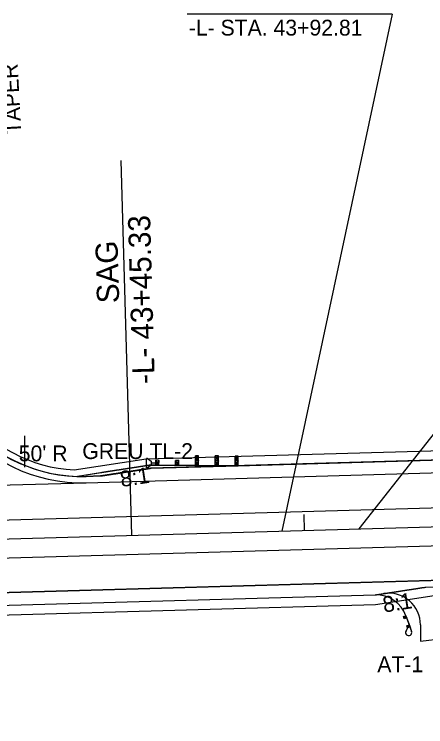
# Model space of a CAD drawing. Extents: x 1755545 to 1761252, y 736169 to 737766.
# Drawn here: x 1758991.6 to 1759121.4, y 736960.3 to 737185.3 of the extents above; entities that cross this region are included whole.
import ezdxf

# ---------------------------------------------------------------- set-up
doc = ezdxf.new("R2010")
doc.units = 0
for name, color, linetype in [('Exist Contamination Potential Cell', 7, 'Continuous'), ('Old_Level_1', 7, 'Continuous'), ('Old_Level_15', 7, 'Continuous'), ('Prop Dimension', 7, 'Continuous'), ('Prop Guardrail', 7, 'Continuous'), ('Prop Guardrail Anchor Unit CELL', 7, 'Continuous'), ('Prop Horizontal Alignment', 7, 'Continuous'), ('Prop Horizontal Alignment Tick Small', 7, 'Continuous'), ('Prop Lane Lines', 7, 'Continuous'), ('Prop Paved Shoulder', 7, 'Continuous'), ('Prop Shade Light', 7, 'Continuous'), ('Scratch_Level_5', 7, 'Continuous'), ('Scratch_Level_6', 7, 'Continuous')]:
    doc.layers.add(name, color=color, linetype=linetype)

msp = doc.modelspace()

# ---------------------------------------------------------------- linework, layer by layer
at = {"layer": 'Exist Contamination Potential Cell'}
for p, q in [((1759014.29, 737037.34), (1760207.22, 737071.22)), ((1757498.66, 736960.29), (1760222.11, 737037.63))]:
    msp.add_line(p, q, dxfattribs=at)
msp.add_arc((1759012.87, 737087.32), 50, 216.7448, 271.6265, dxfattribs=at)
at = {"layer": 'Old_Level_1'}
for p, q in [((1759119.74, 736992.48), (1759119.75, 736987.31)), ((1759119.75, 736987.31), (1759134.95, 736989.05))]:
    msp.add_line(p, q, dxfattribs=at)
msp.add_arc((1759109.74, 736992.46), 10, 0.1161, 98.7516, dxfattribs=at)
at = {"layer": 'Old_Level_15'}
msp.add_line((1759025.17, 737139.07), (1759028.53, 737020.74), dxfattribs=at)
at = {"layer": 'Prop Dimension'}
for p, q in [((1759110.79, 737185.26), (1759046.14, 737185.26)), ((1759110.79, 737185.26), (1759075.99, 737022.09)), ((1759169.57, 737111.19), (1759100.35, 737022.78))]:
    msp.add_line(p, q, dxfattribs=at)
at = {"layer": 'Prop Guardrail'}
for p, q in [((1759211.17, 737046.94), (1759062.23, 737042.71)), ((1758905.56, 736996.24), (1759105.48, 737001.92))]:
    msp.add_line(p, q, dxfattribs=at)
msp.add_arc((1759105.76, 736991.92), 10, 20.0067, 91.6265, dxfattribs=at)
at = {"layer": 'Prop Guardrail Anchor Unit CELL'}
for p, q in [((1759048.73, 737042.81), (1759048.76, 737045.84)), ((1759048.74, 737044.33), (1759049.76, 737045.84)), ((1759049.76, 737045.84), (1759048.76, 737045.84)), ((1759048.76, 737045.84), (1759049.74, 737044.32)), ((1759049.73, 737042.8), (1759049.76, 737045.84)), ((1759054.98, 737042.76), (1759055.01, 737045.8)), ((1759054.99, 737044.28), (1759056.01, 737045.79)), ((1759056.01, 737045.79), (1759055.01, 737045.8)), ((1759055.01, 737045.8), (1759055.99, 737044.27)), ((1759055.98, 737042.75), (1759056.01, 737045.79)), ((1759061.23, 737042.71), (1759061.26, 737045.75)), ((1759061.24, 737044.23), (1759062.26, 737045.74)), ((1759062.26, 737045.74), (1759061.26, 737045.75)), ((1759061.26, 737045.75), (1759062.24, 737044.22)), ((1759062.23, 737042.71), (1759062.26, 737045.74)), ((1759033.27, 737042.08), (1759033.3, 737045.02)), ((1759033.61, 737045.02), (1759033.3, 737045.02)), ((1759033.61, 737045.02), (1759034.77, 737044.15)), ((1759034.77, 737044.15), (1759034.76, 737042.93)), ((1759034.77, 737043.65), (1759036.24, 737043.63)), ((1759036.23, 737042.9), (1759036.25, 737044.42)), ((1759037.24, 737044.41), (1759036.23, 737042.9)), ((1759037.23, 737042.89), (1759036.24, 737044.42)), ((1759037.25, 737044.41), (1759036.25, 737044.42)), ((1759037.23, 737042.89), (1759037.25, 737044.41)), ((1759042.48, 737042.86), (1759042.49, 737044.37)), ((1759043.49, 737044.37), (1759042.48, 737042.86)), ((1759043.5, 737044.37), (1759042.49, 737044.37)), ((1759043.48, 737042.85), (1759042.49, 737044.37)), ((1759043.48, 737042.85), (1759043.5, 737044.37)), ((1759049.74, 737044.32), (1759048.73, 737042.81)), ((1759049.74, 737044.32), (1759048.74, 737044.33)), ((1759049.73, 737042.8), (1759048.74, 737044.33)), ((1759055.99, 737044.27), (1759054.98, 737042.76)), ((1759055.99, 737044.27), (1759054.99, 737044.28)), ((1759055.98, 737042.75), (1759054.99, 737044.28)), ((1759062.24, 737044.22), (1759061.23, 737042.71)), ((1759062.24, 737044.22), (1759061.24, 737044.23)), ((1759062.23, 737042.71), (1759061.24, 737044.23)), ((1759033.58, 737042.08), (1759033.27, 737042.08)), ((1759034.76, 737042.93), (1759033.58, 737042.08)), ((1759036.23, 737042.91), (1759034.76, 737042.93)), ((1759037.23, 737042.89), (1759036.23, 737042.9)), ((1759036.73, 737042.9), (1759061.73, 737042.71)), ((1759043.48, 737042.85), (1759042.48, 737042.86)), ((1759049.73, 737042.8), (1759048.73, 737042.81)), ((1759055.98, 737042.75), (1759054.98, 737042.76)), ((1759062.23, 737042.71), (1759061.23, 737042.71)), ((1759114.4, 736995.07), (1759115.16, 736995.34)), ((1759114.64, 736994.41), (1759114.4, 736995.07)), ((1759115.4, 736994.69), (1759114.4, 736995.07)), ((1759115.16, 736995.34), (1759114.64, 736994.41)), ((1759115.4, 736994.69), (1759114.64, 736994.41)), ((1759115.16, 736995.34), (1759116.37, 736992.01)), ((1759115.16, 736995.34), (1759115.4, 736994.69)), ((1759115.2, 736990.6), (1759115.8, 736991.52)), ((1759115.47, 736992.15), (1759116.22, 736992.42)), ((1759115.71, 736991.49), (1759115.47, 736992.15)), ((1759116.46, 736991.76), (1759115.47, 736992.15)), ((1759116.22, 736992.42), (1759115.71, 736991.49)), ((1759116.46, 736991.76), (1759115.71, 736991.49)), ((1759116.46, 736991.76), (1759116.13, 736991.64)), ((1759116.46, 736991.76), (1759116.13, 736991.64)), ((1759116.22, 736992.42), (1759116.46, 736991.76)), ((1759116.42, 736991.89), (1759116.37, 736992.01)), ((1759116.37, 736992.01), (1759116.96, 736990.4)), ((1759116.42, 736991.89), (1759116.37, 736992.01))]:
    msp.add_line(p, q, dxfattribs=at)
msp.add_ellipse((1759116.03, 736990.06), major_axis=(0.933, 0.34), ratio=0.995379, start_param=2.210226, end_param=6.283185, dxfattribs=at)
at = {"layer": 'Prop Horizontal Alignment'}
msp.add_line((1757285.64, 736971.25), (1760282.69, 737056.35), dxfattribs=at)
at = {"layer": 'Prop Horizontal Alignment Tick Small'}
msp.add_line((1759083.17, 737022.29), (1759083.03, 737027.29), dxfattribs=at)
at = {"layer": 'Prop Lane Lines'}
for p, q in [((1757285.47, 736977.25), (1760207.53, 737060.22)), ((1757285.81, 736965.25), (1760207.87, 737048.23)), ((1758821.01, 737031.85), (1759014.29, 737037.34))]:
    msp.add_line(p, q, dxfattribs=at)
at = {"layer": 'Prop Paved Shoulder'}
for p, q in [((1758994.85, 737052.17), (1758994.78, 737042.25)), ((1759062.23, 737042.71), (1759211.18, 737046.94)), ((1759034.76, 737042.93), (1759011.49, 737039.34)), ((1759034.76, 737042.93), (1759062.23, 737042.71)), ((1759121.42, 737004.37), (1760222.17, 737035.63)), ((1758905.56, 736996.24), (1759105.48, 737001.92))]:
    msp.add_line(p, q, dxfattribs=at)
msp.add_arc((1759012.87, 737087.32), 48, 216.7448, 268.3507, dxfattribs=at)
for points in [[(1759034.76, 737042.93), (1759034.55, 737042.89), (1759034.33, 737042.86), (1759034.12, 737042.83), (1759033.9, 737042.79), (1759033.69, 737042.76), (1759033.47, 737042.73), (1759033.25, 737042.69), (1759033.04, 737042.66), (1759032.82, 737042.63), (1759032.61, 737042.59), (1759032.39, 737042.56), (1759032.18, 737042.53), (1759031.96, 737042.5), (1759031.75, 737042.46), (1759031.53, 737042.43), (1759031.32, 737042.4), (1759031.1, 737042.36), (1759030.89, 737042.33), (1759030.67, 737042.3), (1759030.46, 737042.26), (1759030.24, 737042.23), (1759030.02, 737042.2), (1759029.81, 737042.16), (1759029.59, 737042.13), (1759029.38, 737042.1), (1759029.16, 737042.06), (1759028.95, 737042.03), (1759028.73, 737042), (1759028.52, 737041.96), (1759028.3, 737041.93), (1759028.09, 737041.9), (1759027.87, 737041.87), (1759027.66, 737041.83), (1759027.44, 737041.8), (1759027.22, 737041.77), (1759027.01, 737041.73), (1759026.79, 737041.7), (1759026.58, 737041.67), (1759026.36, 737041.63), (1759026.15, 737041.6), (1759025.93, 737041.57), (1759025.72, 737041.53), (1759025.5, 737041.5), (1759025.29, 737041.47), (1759025.07, 737041.43), (1759024.86, 737041.4), (1759024.64, 737041.37), (1759024.43, 737041.33), (1759024.21, 737041.3), (1759023.99, 737041.27), (1759023.78, 737041.24), (1759023.56, 737041.2), (1759023.35, 737041.17), (1759023.13, 737041.14), (1759022.92, 737041.1), (1759022.7, 737041.07), (1759022.49, 737041.04), (1759022.27, 737041), (1759022.06, 737040.97), (1759021.84, 737040.94), (1759021.63, 737040.9), (1759021.41, 737040.87), (1759021.19, 737040.84), (1759020.98, 737040.8), (1759020.76, 737040.77), (1759020.55, 737040.74), (1759020.33, 737040.7), (1759020.12, 737040.67), (1759019.9, 737040.64), (1759019.69, 737040.61), (1759019.47, 737040.57), (1759019.26, 737040.54), (1759018.83, 737040.47)], [(1759105.48, 737001.92), (1759105.7, 737001.95), (1759105.91, 737001.98), (1759106.13, 737002.02), (1759106.34, 737002.05), (1759106.56, 737002.08), (1759106.77, 737002.12), (1759106.99, 737002.15), (1759107.2, 737002.18), (1759107.42, 737002.22), (1759107.63, 737002.25), (1759107.85, 737002.28), (1759108.06, 737002.32), (1759108.28, 737002.35), (1759108.5, 737002.38), (1759108.71, 737002.41), (1759108.93, 737002.45), (1759109.14, 737002.48), (1759109.36, 737002.51), (1759109.57, 737002.55), (1759109.79, 737002.58), (1759110, 737002.61), (1759110.22, 737002.65), (1759110.43, 737002.68), (1759110.65, 737002.71), (1759110.86, 737002.75), (1759111.08, 737002.78), (1759111.3, 737002.81), (1759111.51, 737002.85), (1759111.73, 737002.88), (1759111.94, 737002.91), (1759112.16, 737002.95), (1759112.37, 737002.98), (1759112.59, 737003.01), (1759112.8, 737003.04), (1759113.02, 737003.08), (1759113.23, 737003.11), (1759113.45, 737003.14), (1759113.66, 737003.18), (1759113.88, 737003.21), (1759114.09, 737003.24), (1759114.31, 737003.28), (1759114.53, 737003.31), (1759114.74, 737003.34), (1759114.96, 737003.38), (1759115.17, 737003.41), (1759115.39, 737003.44), (1759115.6, 737003.48), (1759115.82, 737003.51), (1759116.03, 737003.54), (1759116.25, 737003.58), (1759116.46, 737003.61), (1759116.68, 737003.64), (1759116.89, 737003.67), (1759117.11, 737003.71), (1759117.33, 737003.74), (1759117.54, 737003.77), (1759117.76, 737003.81), (1759117.97, 737003.84), (1759118.19, 737003.87), (1759118.4, 737003.91), (1759118.62, 737003.94), (1759118.83, 737003.97), (1759119.05, 737004.01), (1759119.26, 737004.04), (1759119.48, 737004.07), (1759119.69, 737004.11), (1759119.91, 737004.14), (1759120.13, 737004.17), (1759120.34, 737004.21), (1759120.56, 737004.24), (1759120.77, 737004.27), (1759120.99, 737004.3), (1759121.42, 737004.37)]]:
    msp.add_spline(points, degree=3, dxfattribs=at)
at = {"layer": 'Prop Shade Light'}
for p, q in [((1759014.29, 737037.34), (1760207.22, 737071.22)), ((1759238.63, 737047.72), (1759034.78, 737041.93)), ((1759032.55, 737042.59), (1759032, 737042.5)), ((1759034.76, 737042.93), (1759034.73, 737042.92)), ((1759062.23, 737042.71), (1759034.76, 737042.93)), ((1759034.78, 737041.93), (1759062.23, 737042.71)), ((1759018.83, 737040.47), (1759011.49, 737039.34)), ((1759018.84, 737039.47), (1759014.23, 737039.34)), ((1759014.23, 737039.34), (1759018.84, 737039.47)), ((1760222.11, 737037.63), (1757498.66, 736960.29)), ((1759121.42, 737004.37), (1760222.17, 737035.63)), ((1758878.1, 736995.46), (1759105.48, 737001.92))]:
    msp.add_line(p, q, dxfattribs=at)
for points in [[(1759026.51, 737041.66), (1759026.33, 737041.63), (1759024.14, 737041.29)], [(1759027.99, 737041.88), (1759027.53, 737041.81), (1759027.34, 737041.78)], [(1759033.41, 737042.72), (1759033.06, 737042.66), (1759032.68, 737042.61)]]:
    msp.add_lwpolyline(points, dxfattribs=at)
for radius, start in [(50, 216.7448), (48, 216.7448), (48, 268.3507)]:
    msp.add_arc((1759012.87, 737087.32), radius, start, 271.6265, dxfattribs=at)
for points in [[(1759024.14, 737041.29), (1759024.09, 737041.28), (1759024.04, 737041.28), (1759023.99, 737041.27), (1759023.92, 737041.26), (1759023.85, 737041.25), (1759023.78, 737041.24), (1759023.71, 737041.22), (1759023.64, 737041.21), (1759023.56, 737041.2), (1759023.49, 737041.19), (1759023.42, 737041.18), (1759023.35, 737041.17), (1759023.28, 737041.16), (1759023.2, 737041.15), (1759023.13, 737041.14), (1759023.06, 737041.12), (1759022.99, 737041.11), (1759022.92, 737041.1), (1759022.85, 737041.09), (1759022.77, 737041.08), (1759022.7, 737041.07), (1759022.63, 737041.06), (1759022.56, 737041.05), (1759022.49, 737041.04), (1759022.42, 737041.03), (1759022.34, 737041.01), (1759022.27, 737041), (1759022.2, 737040.99), (1759022.13, 737040.98), (1759022.06, 737040.97), (1759021.98, 737040.96), (1759021.91, 737040.95), (1759021.84, 737040.94), (1759021.77, 737040.93), (1759021.7, 737040.91), (1759021.63, 737040.9), (1759021.55, 737040.89), (1759021.48, 737040.88), (1759021.41, 737040.87), (1759021.34, 737040.86), (1759021.27, 737040.85), (1759021.19, 737040.84), (1759021.12, 737040.83), (1759021.05, 737040.82), (1759020.98, 737040.8), (1759020.91, 737040.79), (1759020.84, 737040.78), (1759020.76, 737040.77), (1759020.69, 737040.76), (1759020.62, 737040.75), (1759020.55, 737040.74), (1759020.48, 737040.73), (1759020.41, 737040.72), (1759020.33, 737040.7), (1759020.26, 737040.69), (1759020.19, 737040.68), (1759020.12, 737040.67), (1759020.05, 737040.66), (1759019.97, 737040.65), (1759019.9, 737040.64), (1759019.83, 737040.63), (1759019.76, 737040.62), (1759019.69, 737040.61), (1759019.62, 737040.59), (1759019.54, 737040.58), (1759019.47, 737040.57), (1759019.4, 737040.56), (1759019.33, 737040.55), (1759019.26, 737040.54), (1759019.11, 737040.52), (1759018.97, 737040.49), (1759018.83, 737040.47)], [(1759029.45, 737042.11), (1759029.43, 737042.1), (1759029.4, 737042.1), (1759029.38, 737042.1), (1759029.31, 737042.09), (1759029.23, 737042.08), (1759029.16, 737042.06), (1759029.09, 737042.05), (1759029.02, 737042.04), (1759028.95, 737042.03), (1759028.88, 737042.02), (1759028.8, 737042.01), (1759028.73, 737042), (1759028.66, 737041.99), (1759028.59, 737041.98), (1759028.52, 737041.96), (1759028.45, 737041.95), (1759028.37, 737041.94), (1759028.3, 737041.93), (1759028.23, 737041.92), (1759028.16, 737041.91), (1759028.09, 737041.9), (1759028.05, 737041.89), (1759028.02, 737041.89), (1759027.99, 737041.88)], [(1759034.73, 737042.92), (1759034.67, 737042.91), (1759034.61, 737042.9), (1759034.55, 737042.89), (1759034.48, 737042.88), (1759034.4, 737042.87), (1759034.33, 737042.86), (1759034.26, 737042.85), (1759034.19, 737042.84), (1759034.12, 737042.83), (1759034.04, 737042.82), (1759033.97, 737042.8), (1759033.9, 737042.79), (1759033.83, 737042.78), (1759033.76, 737042.77), (1759033.69, 737042.76), (1759033.61, 737042.75), (1759033.54, 737042.74), (1759033.47, 737042.73), (1759033.45, 737042.72), (1759033.43, 737042.72), (1759033.41, 737042.72)]]:
    msp.add_open_spline(points, degree=3, dxfattribs=at)
for points in [[(1759029.46, 737041.11), (1759029.39, 737041.1), (1759029.18, 737041.06), (1759028.96, 737041.03), (1759028.75, 737041), (1759028.53, 737040.97), (1759028.32, 737040.93), (1759028.1, 737040.9), (1759027.88, 737040.87), (1759027.67, 737040.83), (1759027.45, 737040.8), (1759027.24, 737040.77), (1759027.02, 737040.73), (1759026.81, 737040.7), (1759026.59, 737040.67), (1759026.38, 737040.63), (1759026.16, 737040.6), (1759025.95, 737040.57), (1759025.73, 737040.53), (1759025.52, 737040.5), (1759025.3, 737040.47), (1759025.09, 737040.43), (1759024.87, 737040.4), (1759024.65, 737040.37), (1759024.44, 737040.34), (1759024.22, 737040.3), (1759024.15, 737040.29)], [(1759024.15, 737040.29), (1759024.22, 737040.3), (1759024.44, 737040.34), (1759024.65, 737040.37), (1759024.87, 737040.4), (1759025.09, 737040.43), (1759025.3, 737040.47), (1759025.52, 737040.5), (1759025.73, 737040.53), (1759025.95, 737040.57), (1759026.16, 737040.6), (1759026.38, 737040.63), (1759026.59, 737040.67), (1759026.81, 737040.7), (1759027.02, 737040.73), (1759027.24, 737040.77), (1759027.45, 737040.8), (1759027.67, 737040.83), (1759027.88, 737040.87), (1759028.1, 737040.9), (1759028.32, 737040.93), (1759028.53, 737040.97), (1759028.75, 737041), (1759028.96, 737041.03), (1759029.18, 737041.06), (1759029.39, 737041.1), (1759029.46, 737041.11)], [(1759027.34, 737041.78), (1759027.22, 737041.77), (1759027.01, 737041.73), (1759026.79, 737041.7), (1759026.58, 737041.67), (1759026.51, 737041.66)], [(1759032, 737042.5), (1759031.96, 737042.5), (1759031.75, 737042.46), (1759031.53, 737042.43), (1759031.32, 737042.4), (1759031.1, 737042.36), (1759030.89, 737042.33), (1759030.67, 737042.3), (1759030.46, 737042.26), (1759030.24, 737042.23), (1759030.02, 737042.2), (1759029.81, 737042.16), (1759029.59, 737042.13), (1759029.45, 737042.11)], [(1759034.78, 737041.93), (1759034.56, 737041.89), (1759034.35, 737041.86), (1759034.13, 737041.83), (1759033.91, 737041.79), (1759033.7, 737041.76), (1759033.48, 737041.73), (1759033.27, 737041.69), (1759033.05, 737041.66), (1759032.84, 737041.63), (1759032.62, 737041.6), (1759032.41, 737041.56), (1759032.19, 737041.53), (1759031.98, 737041.5), (1759031.76, 737041.46), (1759031.55, 737041.43), (1759031.33, 737041.4), (1759031.12, 737041.36), (1759030.9, 737041.33), (1759030.68, 737041.3), (1759030.47, 737041.26), (1759030.25, 737041.23), (1759030.04, 737041.2), (1759029.82, 737041.16), (1759029.61, 737041.13), (1759029.46, 737041.11)], [(1759029.46, 737041.11), (1759029.61, 737041.13), (1759029.82, 737041.16), (1759030.04, 737041.2), (1759030.25, 737041.23), (1759030.47, 737041.26), (1759030.68, 737041.3), (1759030.9, 737041.33), (1759031.12, 737041.36), (1759031.33, 737041.4), (1759031.55, 737041.43), (1759031.76, 737041.46), (1759031.98, 737041.5), (1759032.19, 737041.53), (1759032.41, 737041.56), (1759032.62, 737041.6), (1759032.84, 737041.63), (1759033.05, 737041.66), (1759033.27, 737041.69), (1759033.48, 737041.73), (1759033.7, 737041.76), (1759033.91, 737041.79), (1759034.13, 737041.83), (1759034.35, 737041.86), (1759034.56, 737041.89), (1759034.78, 737041.93)], [(1759032.68, 737042.61), (1759032.61, 737042.59), (1759032.55, 737042.59)], [(1759024.15, 737040.29), (1759024.01, 737040.27), (1759023.79, 737040.24), (1759023.58, 737040.2), (1759023.36, 737040.17), (1759023.15, 737040.14), (1759022.93, 737040.1), (1759022.72, 737040.07), (1759022.5, 737040.04), (1759022.29, 737040), (1759022.07, 737039.97), (1759021.85, 737039.94), (1759021.64, 737039.9), (1759021.42, 737039.87), (1759021.21, 737039.84), (1759020.99, 737039.8), (1759020.78, 737039.77), (1759020.56, 737039.74), (1759020.35, 737039.71), (1759020.13, 737039.67), (1759019.92, 737039.64), (1759019.7, 737039.61), (1759019.49, 737039.57), (1759019.27, 737039.54), (1759018.84, 737039.47)], [(1759018.84, 737039.47), (1759019.27, 737039.54), (1759019.49, 737039.57), (1759019.7, 737039.61), (1759019.92, 737039.64), (1759020.13, 737039.67), (1759020.35, 737039.71), (1759020.56, 737039.74), (1759020.78, 737039.77), (1759020.99, 737039.8), (1759021.21, 737039.84), (1759021.42, 737039.87), (1759021.64, 737039.9), (1759021.85, 737039.94), (1759022.07, 737039.97), (1759022.29, 737040), (1759022.5, 737040.04), (1759022.72, 737040.07), (1759022.93, 737040.1), (1759023.15, 737040.14), (1759023.36, 737040.17), (1759023.58, 737040.2), (1759023.79, 737040.24), (1759024.01, 737040.27), (1759024.15, 737040.29)], [(1759105.48, 737001.92), (1759105.7, 737001.95), (1759105.91, 737001.98), (1759106.13, 737002.02), (1759106.34, 737002.05), (1759106.56, 737002.08), (1759106.77, 737002.12), (1759106.99, 737002.15), (1759107.2, 737002.18), (1759107.42, 737002.22), (1759107.63, 737002.25), (1759107.85, 737002.28), (1759108.06, 737002.32), (1759108.28, 737002.35), (1759108.5, 737002.38), (1759108.71, 737002.41), (1759108.93, 737002.45), (1759109.14, 737002.48), (1759109.36, 737002.51), (1759109.57, 737002.55), (1759109.79, 737002.58), (1759110, 737002.61), (1759110.22, 737002.65), (1759110.43, 737002.68), (1759110.65, 737002.71), (1759110.79, 737002.74)], [(1759110.79, 737002.74), (1759110.86, 737002.75), (1759111.08, 737002.78), (1759111.3, 737002.81), (1759111.51, 737002.85), (1759111.73, 737002.88), (1759111.94, 737002.91), (1759112.16, 737002.95), (1759112.37, 737002.98), (1759112.59, 737003.01), (1759112.8, 737003.04), (1759113.02, 737003.08), (1759113.23, 737003.11), (1759113.45, 737003.14), (1759113.66, 737003.18), (1759113.88, 737003.21), (1759114.09, 737003.24), (1759114.31, 737003.28), (1759114.53, 737003.31), (1759114.74, 737003.34), (1759114.96, 737003.38), (1759115.17, 737003.41), (1759115.39, 737003.44), (1759115.6, 737003.48), (1759115.82, 737003.51), (1759116.03, 737003.54), (1759116.1, 737003.55)], [(1759116.1, 737003.55), (1759116.25, 737003.58), (1759116.46, 737003.61), (1759116.68, 737003.64), (1759116.89, 737003.67), (1759117.11, 737003.71), (1759117.33, 737003.74), (1759117.54, 737003.77), (1759117.76, 737003.81), (1759117.97, 737003.84), (1759118.19, 737003.87), (1759118.4, 737003.91), (1759118.62, 737003.94), (1759118.83, 737003.97), (1759119.05, 737004.01), (1759119.26, 737004.04), (1759119.48, 737004.07), (1759119.69, 737004.11), (1759119.91, 737004.14), (1759120.13, 737004.17), (1759120.34, 737004.21), (1759120.56, 737004.24), (1759120.77, 737004.27), (1759120.99, 737004.3), (1759121.42, 737004.37)]]:
    msp.add_spline(points, degree=3, dxfattribs=at)
at = {"layer": 'Scratch_Level_5'}
for p, q in [((1759061.73, 737042.69), (1759211.67, 737046.95)), ((1759034.77, 737041.94), (1759061.73, 737042.69)), ((1758905.56, 736996.24), (1759105.48, 737001.92)), ((1759115.16, 736995.34), (1759116.96, 736990.4))]:
    msp.add_line(p, q, dxfattribs=at)
msp.add_arc((1759105.76, 736991.92), 10, 20.0067, 91.6265, dxfattribs=at)
at = {"layer": 'Scratch_Level_6'}
for p, q in [((1759033.21, 737044.88), (1759238.55, 737050.71)), ((1759010.48, 737041.39), (1759033.21, 737044.88)), ((1759105.57, 736998.92), (1759129.47, 737002.6)), ((1758878.19, 736992.46), (1759105.57, 736998.92))]:
    msp.add_line(p, q, dxfattribs=at)
msp.add_arc((1759012.87, 737087.32), 46, 216.7448, 267.0271, dxfattribs=at)

# ---------------------------------------------------------------- texts
at = {"layer": 'Old_Level_15'}
for s, p in [('-L- 43+45.33', (1759035.94, 737068.59)), ('SAG', (1759024.71, 737094.1))]:
    msp.add_text(s, height=7, rotation=91.6265, dxfattribs=at).set_placement(p)
at = {"layer": 'Prop Dimension'}
for s, rotation, p in [('-L- STA. 43+92.81', 360, (1759046.64, 737178.53)), ('TAPER', 93.1274, (1758993.84, 737147.53)), ("50' R", 360, (1758992.99, 737044.1)), ('8:1', 8.7516, (1759025.38, 737035.96)), ('8:1', 8.7516, (1759108.25, 736996.34))]:
    msp.add_text(s, height=5, rotation=rotation, dxfattribs=at).set_placement(p)
at = {"layer": 'Prop Guardrail Anchor Unit CELL'}
for s, p in [('GREU TL-2', (1759013.04, 737044.82)), ('AT-1', (1759106.13, 736977.52))]:
    msp.add_text(s, height=5, rotation=360, dxfattribs=at).set_placement(p)

doc.saveas('drawing.dxf')
